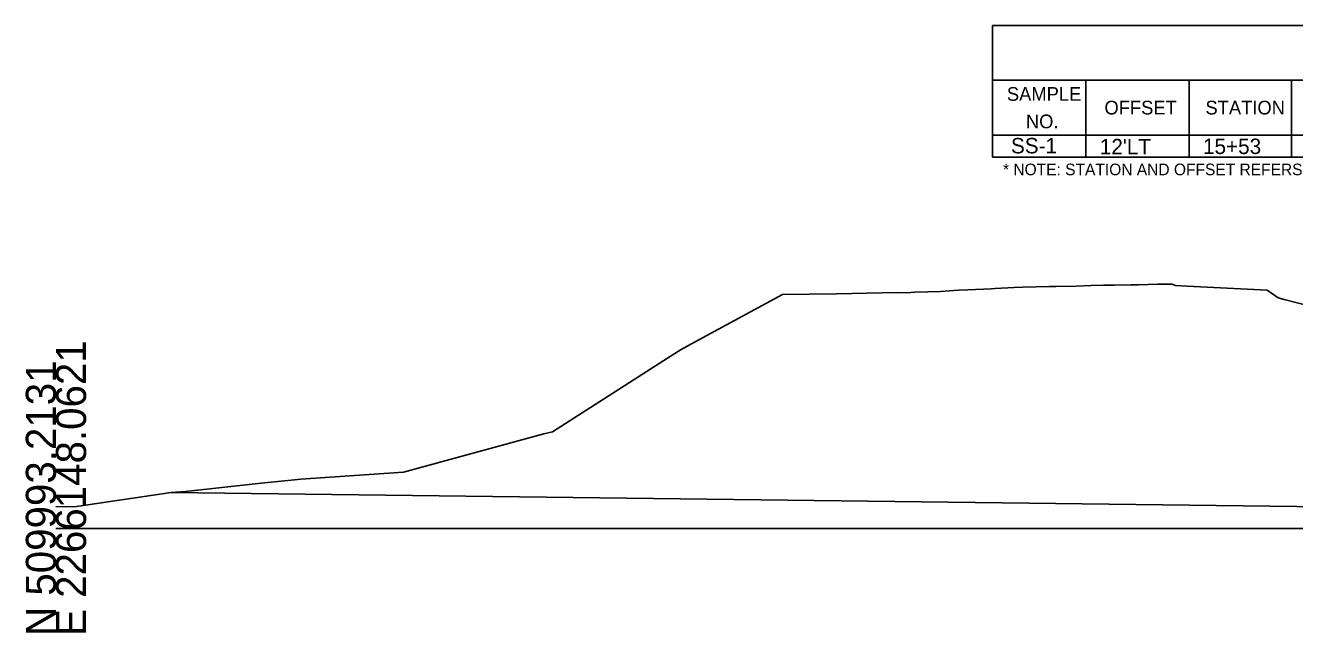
# Model space of a CAD drawing. Extents: x -827 to 2303, y -169 to 9934.
# Drawn here: x -2.8 to 115.1, y 5990.3 to 6046.8 of the extents above; entities that cross this region are included whole.
import ezdxf

# ---------------------------------------------------------------- set-up
doc = ezdxf.new("R2010")
doc.units = 0
for name, color, linetype in [('Default', 7, 'Continuous'), ('Exist Cross Section Cell', 7, 'Continuous'), ('Exist XS Ground Line', 7, 'Continuous'), ('Geotech Sheets and Borders Cell', 7, 'Continuous'), ('Prop DirtTable_ Soil Test Results - Tx (Sample Data)', 7, 'Continuous'), ('Prop Road Sect_ Material - Contact (General - Major)', 7, 'Continuous')]:
    doc.layers.add(name, color=color, linetype=linetype)

msp = doc.modelspace()

# ---------------------------------------------------------------- linework, layer by layer
at = {"layer": 'Exist Cross Section Cell'}
msp.add_line((0, 6000), (150, 6000), dxfattribs=at)
at = {"layer": 'Exist XS Ground Line'}
msp.add_lwpolyline([(0, 6002.01), (1.92, 6002.03), (10.71, 6003.34), (12.05, 6003.44), (19.08, 6004.21), (22.17, 6004.52), (22.76, 6004.56), (32.3, 6005.23), (45.35, 6008.78), (46.15, 6008.98), (57.29, 6016.09), (58.11, 6016.62), (60.11, 6017.72), (67.53, 6021.73), (72.55, 6021.82), (78.19, 6021.92), (79.07, 6021.89), (79.46, 6021.92), (79.84, 6021.95), (81.04, 6021.99), (82.22, 6022.03), (83.91, 6022.14), (84.76, 6022.19), (86.94, 6022.28), (87.28, 6022.3), (89.07, 6022.38), (89.87, 6022.42), (91.12, 6022.46), (92.34, 6022.49), (92.95, 6022.5), (94.85, 6022.53), (96.24, 6022.57), (97.37, 6022.6), (98.41, 6022.62), (99.91, 6022.64), (100.61, 6022.65), (102.44, 6022.69), (103.74, 6022.69), (104.06, 6022.58), (105.15, 6022.53), (112.59, 6022.14), (113.63, 6021.43), (114.17, 6021.29), (118.18, 6020.24)], dxfattribs=at)
at = {"layer": 'Geotech Sheets and Borders Cell'}
for p, q in [((87.07, 6046.76), (87.07, 6036.56)), ((87.07, 6046.76), (214.87, 6046.76)), ((87.07, 6041.66), (214.87, 6041.66)), ((95.75, 6041.66), (95.75, 6034.5)), ((105.36, 6041.66), (105.36, 6034.5)), ((114.87, 6041.66), (114.87, 6034.5)), ((87.07, 6036.56), (214.87, 6036.56)), ((87.07, 6036.56), (214.87, 6036.56)), ((87.07, 6036.56), (87.07, 6034.5)), ((87.07, 6034.5), (214.87, 6034.5)), ((87.07, 6034.5), (214.87, 6034.5))]:
    msp.add_line(p, q, dxfattribs=at)
at = {"layer": 'Prop Road Sect_ Material - Contact (General - Major)'}
msp.add_line((10.71, 6003.34), (205.95, 6000.9), dxfattribs=at)

# ---------------------------------------------------------------- texts
at = {"layer": 'Default'}
msp.add_text('-', height=0.0001, dxfattribs=at).set_placement((0, 6000))
msp.add_text('-', height=0.0001, dxfattribs=at).set_placement((0, 6000))
at = {"layer": 'Exist Cross Section Cell'}
for s, p in [('E 2266148.0621', (2.8, 5990)), ('N 509993.2131', (0, 5990))]:
    msp.add_text(s, height=2.8, rotation=90, dxfattribs=at).set_placement(p)
at = {"layer": 'Geotech Sheets and Borders Cell'}
for s, p in [('SAMPLE', (88.4, 6039.75)), ('OFFSET', (97.47, 6038.48)), ('STATION', (106.86, 6038.48)), ('NO.', (90.17, 6037.2))]:
    msp.add_text(s, height=1.275, dxfattribs=at).set_placement(p)
at = {"layer": 'Prop DirtTable_ Soil Test Results - Tx (Sample Data)'}
for s, height, p in [('SS-1', 1.44, (88.78, 6034.86)), ("12'LT", 1.44, (97.04, 6034.77)), ('15+53', 1.44, (106.63, 6034.8)), ('* NOTE: STATION AND OFFSET REFERS TO -SR1- ALIGNMENT', 1.08, (88.04, 6032.83))]:
    msp.add_text(s, height=height, dxfattribs=at).set_placement(p)

doc.saveas('drawing.dxf')
